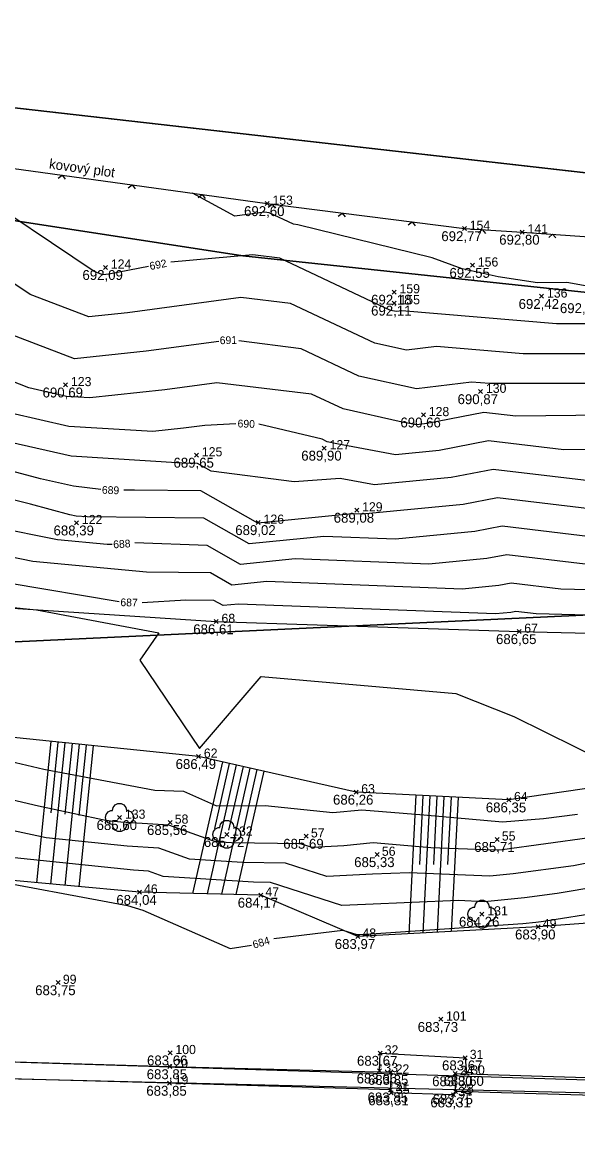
# Model space of a CAD drawing. Extents: x -439750 to -439180, y -1258684 to -1258308.
# Drawn here: x -439502.17 to -439486.43, y -1258511.26 to -1258479.7 of the extents above; entities that cross this region are included whole.
import ezdxf

# ---------------------------------------------------------------- set-up
doc = ezdxf.new("R2010")
doc.units = 0
for name, color, linetype in [('BODY', 7, 'Continuous'), ('CISBOD', 7, 'Continuous'), ('HRANA', 7, 'Continuous'), ('KATASTER', 7, 'Continuous'), ('POLOHOPIS', 7, 'Continuous'), ('SRAFY', 7, 'Continuous'), ('UOV', 7, 'Continuous'), ('VRSTEV', 7, 'Continuous'), ('VYSKY', 7, 'Continuous')]:
    doc.layers.add(name, color=color, linetype=linetype)

# ---------------------------------------------------------------- blocks, each defined once
blk = doc.blocks.new('313')
for points in [[(2, 0), (1.9, -0.43), (1.62, -0.78), (1.22, -0.97), (1, -1), (0.9, -1.43), (0.62, -1.78), (0.22, -1.97), (-0.23, -1.97), (-0.63, -1.78), (-0.91, -1.43), (-1.01, -1), (-1.23, -0.97), (-1.63, -0.78), (-1.91, -0.43), (-2.01, 0), (-1.91, 0.43), (-1.63, 0.78), (-1.23, 0.97), (-1.01, 1), (-0.91, 1.43), (-0.63, 1.78), (-0.23, 1.97), (0.22, 1.97), (0.62, 1.78), (0.9, 1.43), (1, 1), (1.22, 0.97), (1.62, 0.78), (1.9, 0.43), (2, 0)], [(-0.05, 0), (0, 0), (0.05, 0)]]:
    blk.add_lwpolyline(points)
blk = doc.blocks.new('KRIZEK')
for p, q in [((-2, 0), (2, 0)), ((0, 2), (0, -2))]:
    blk.add_line(p, q)
blk = doc.blocks.new('2123')
blk.add_lwpolyline([(-0.5, -0.5), (0, 0), (0.5, -0.5)])

msp = doc.modelspace()

# ---------------------------------------------------------------- linework, layer by layer
at = {"layer": 'HRANA'}
for points in [[(-439511.54, -1258493.8), (-439507.75, -1258495.43), (-439503.31, -1258496.25), (-439496.67, -1258496.69), (-439488.09, -1258496.97), (-439481.73, -1258497.12), (-439481.16, -1258497.23), (-439475.66, -1258497.77), (-439471.49, -1258498.09)], [(-439471.88, -1258500.9), (-439476.61, -1258500.46), (-439482.49, -1258500.91), (-439485.2, -1258501.28), (-439488.38, -1258501.74), (-439492.71, -1258501.52), (-439497.17, -1258500.51), (-439503.07, -1258499.91), (-439506.02, -1258500.06)], [(-439475.58, -1258504.53), (-439478.3, -1258506.13), (-439479.11, -1258504.72), (-439487.55, -1258505.34), (-439492.66, -1258505.61), (-439495.41, -1258504.44), (-439498.85, -1258504.36), (-439505, -1258503.79), (-439507.43, -1258504.94)]]:
    msp.add_lwpolyline(points, dxfattribs=at)
at = {"layer": 'KATASTER'}
for points in [[(-439462.74, -1258442.73), (-439465.13, -1258459.21), (-439469.01, -1258485.93), (-439514.85, -1258480.71), (-439509.68, -1258462.08), (-439512.86, -1258458.3), (-439516.51, -1258455.4), (-439520.66, -1258452.66), (-439525.5, -1258450.78), (-439531.73, -1258450.85), (-439536.69, -1258451.87), (-439541.07, -1258454.21), (-439546.64, -1258459.47)], [(-439546.64, -1258459.47), (-439541.07, -1258454.21), (-439536.69, -1258451.87), (-439531.73, -1258450.85), (-439525.5, -1258450.78), (-439520.66, -1258452.66), (-439516.51, -1258455.4), (-439512.86, -1258458.3), (-439509.68, -1258462.08), (-439514.85, -1258480.71), (-439515.19, -1258481.93), (-439503.22, -1258485.2), (-439495.92, -1258486.32), (-439485.72, -1258487.41), (-439470.33, -1258487.62), (-439429.22, -1258494.1), (-439415.96, -1258495.89), (-439399.97, -1258496.98), (-439400.54, -1258499.28), (-439484.47, -1258496.42), (-439507.21, -1258497.49), (-439520.19, -1258486.95), (-439538.17, -1258484.88), (-439548.5, -1258497.7)], [(-439548.5, -1258497.7), (-439538.17, -1258484.88), (-439520.19, -1258486.95), (-439507.21, -1258497.49), (-439484.47, -1258496.42), (-439400.54, -1258499.28), (-439387.09, -1258499.74), (-439411.19, -1258562.66), (-439413.56, -1258566.65), (-439437.77, -1258626.82), (-439438.12, -1258627.38), (-439482.75, -1258611.76), (-439518.67, -1258591.95), (-439550.54, -1258581.84), (-439567.51, -1258574.36), (-439597.45, -1258561.13)]]:
    msp.add_lwpolyline(points, dxfattribs=at)
for points in [[(-439515.19, -1258481.93), (-439514.85, -1258480.71), (-439469.01, -1258485.93), (-439399.61, -1258493.83), (-439399.2, -1258493.87), (-439399.97, -1258496.98), (-439415.96, -1258495.89), (-439429.22, -1258494.1), (-439470.33, -1258487.62), (-439485.72, -1258487.41), (-439495.92, -1258486.32), (-439503.22, -1258485.2)], [(-439543.31, -1258507.99), (-439510.11, -1258508.88), (-439509.96, -1258507.11), (-439505.22, -1258507.33), (-439505.26, -1258509.08), (-439479.78, -1258509.87), (-439475.62, -1258505.39), (-439475.25, -1258505.73), (-439479.41, -1258510.21), (-439505.77, -1258509.57), (-439505.73, -1258507.82), (-439509.5, -1258507.65), (-439509.65, -1258509.42), (-439543.32, -1258508.49)]]:
    msp.add_lwpolyline(points, close=True, dxfattribs=at)
at = {"layer": 'POLOHOPIS'}
for points in [[(-439511.93, -1258482.54), (-439503.64, -1258483.68), (-439495.23, -1258484.84), (-439489.64, -1258485.55), (-439488, -1258485.65), (-439480.93, -1258486.14), (-439472.63, -1258486.56)], [(-439491.72, -1258509.46), (-439491.73, -1258509.96), (-439498, -1258509.77), (-439506.04, -1258509.55), (-439505.93, -1258507.56)], [(-439505.93, -1258507.56), (-439505.43, -1258507.59), (-439505.49, -1258509.07), (-439497.99, -1258509.3), (-439491.72, -1258509.46)], [(-439492.04, -1258509.42), (-439492.03, -1258508.92), (-439489.62, -1258509.05), (-439489.58, -1258509.49)], [(-439489.89, -1258510.01), (-439489.95, -1258510.1), (-439491.71, -1258510.04), (-439491.73, -1258509.96)]]:
    msp.add_lwpolyline(points, dxfattribs=at)
msp.add_lwpolyline([(-439475.72, -1258505.59), (-439475.5, -1258505.84), (-439480.09, -1258510.29), (-439489.89, -1258510.01), (-439489.9, -1258509.5), (-439480.3, -1258509.79), (-439476.09, -1258505.71)], close=True, dxfattribs=at)
at = {"layer": 'SRAFY'}
for p, q in [((-439501.355, -1258500.084), (-439501.762, -1258504.09)), ((-439500.957, -1258500.125), (-439501.364, -1258504.127)), ((-439501.156, -1258500.105), (-439501.359, -1258502.107)), ((-439500.559, -1258500.165), (-439500.965, -1258504.164)), ((-439500.758, -1258500.145), (-439500.961, -1258502.145)), ((-439500.36, -1258500.186), (-439500.563, -1258502.184)), ((-439500.161, -1258500.206), (-439500.567, -1258504.201)), ((-439496.495, -1258500.663), (-439497.34, -1258504.395)), ((-439496.105, -1258500.751), (-439496.932, -1258504.405)), ((-439496.3, -1258500.707), (-439496.718, -1258502.553)), ((-439495.91, -1258500.795), (-439496.319, -1258502.602)), ((-439495.715, -1258500.84), (-439496.524, -1258504.414)), ((-439495.324, -1258500.928), (-439496.116, -1258504.424)), ((-439495.52, -1258500.884), (-439495.92, -1258502.651)), ((-439491.016, -1258501.606), (-439491.215, -1258505.534)), ((-439490.816, -1258501.616), (-439490.915, -1258503.57)), ((-439490.616, -1258501.626), (-439490.814, -1258505.512)), ((-439490.416, -1258501.637), (-439490.515, -1258503.569)), ((-439490.217, -1258501.647), (-439490.412, -1258505.491)), ((-439490.017, -1258501.657), (-439490.114, -1258503.569)), ((-439489.817, -1258501.667), (-439490.01, -1258505.47))]:
    msp.add_line(p, q, dxfattribs=at)
at = {"layer": 'UOV'}
msp.add_lwpolyline([(-439484.47, -1258496.42), (-439507.21, -1258497.49), (-439513.68, -1258492.23), (-439512.62, -1258492.23), (-439510.04, -1258487.61), (-439512.85, -1258480.94), (-439399.2, -1258493.87), (-439444.59, -1258496.79), (-439457.07, -1258497.35)], close=True, dxfattribs=at)
at = {"layer": 'VRSTEV'}
for points in [[(-439498.592, -1258486.625), (-439499.716, -1258486.844), (-439499.882, -1258486.862), (-439500.133, -1258486.766), (-439503.739, -1258484.346), (-439504.829, -1258483.901), (-439505.445, -1258483.432)], [(-439472.563, -1258487.239), (-439474.364, -1258487.755), (-439475.068, -1258487.75), (-439481.431, -1258487.77), (-439481.982, -1258487.475), (-439485.316, -1258487.329), (-439486.733, -1258487.079), (-439487.567, -1258487.084), (-439488.686, -1258486.915), (-439489.699, -1258486.689), (-439490.553, -1258486.376), (-439494.362, -1258485.445), (-439494.481, -1258485.427), (-439495.169, -1258485.102), (-439495.299, -1258485.087), (-439496.141, -1258485.2), (-439497.343, -1258484.549)], [(-439496.598, -1258488.747), (-439498.657, -1258489.027), (-439500.691, -1258489.246), (-439503.758, -1258488.068), (-439504.242, -1258487.743), (-439504.714, -1258487.551), (-439506.398, -1258486.559), (-439507.252, -1258486.214), (-439507.761, -1258485.907), (-439508.368, -1258485.633), (-439509.881, -1258484.987)], [(-439496.117, -1258491.08), (-439496.994, -1258491.129), (-439497.598, -1258491.21), (-439498.471, -1258491.304), (-439500.847, -1258491.155), (-439503.327, -1258490.595), (-439503.763, -1258490.479), (-439504.298, -1258490.324), (-439506.612, -1258489.211), (-439507.713, -1258488.761), (-439507.997, -1258488.59), (-439510.978, -1258487.248), (-439511.323, -1258487.078), (-439512.748, -1258486.152)], [(-439472.387, -1258489.02), (-439474.074, -1258489.503), (-439475.335, -1258489.453), (-439480.066, -1258489.43), (-439482.054, -1258489.252), (-439482.296, -1258489.125), (-439483.548, -1258489.103), (-439484.957, -1258489.077), (-439486.022, -1258489.098), (-439487.975, -1258489.098), (-439490.426, -1258488.894), (-439491.279, -1258488.999), (-439492.179, -1258488.799), (-439494.568, -1258487.671), (-439495.977, -1258487.503), (-439499.186, -1258487.936), (-439500.286, -1258488.054), (-439501.945, -1258487.417), (-439503.99, -1258486.045)], [(-439476.105, -1258488.582), (-439480.759, -1258488.607), (-439481.744, -1258488.519), (-439482.151, -1258488.307), (-439482.769, -1258488.296), (-439485.7, -1258488.243), (-439486.167, -1258488.252), (-439487.024, -1258488.252), (-439491.41, -1258487.886), (-439491.566, -1258487.905), (-439491.73, -1258487.868), (-439494.869, -1258486.386), (-439495.638, -1258486.295), (-439497.956, -1258486.501)], [(-439499.942, -1258492.947), (-439500.712, -1258492.853), (-439501.653, -1258492.64), (-439504.346, -1258491.923), (-439506.411, -1258491.327), (-439507.175, -1258491.189), (-439507.403, -1258491.125), (-439509.854, -1258490.5), (-439509.991, -1258490.431), (-439510.441, -1258490.117), (-439512.406, -1258488.742), (-439513.493, -1258488.215)], [(-439475.314, -1258490.305), (-439475.741, -1258490.27), (-439479.372, -1258490.252), (-439482.364, -1258489.984), (-439482.442, -1258489.944), (-439484.031, -1258489.915), (-439484.276, -1258489.92), (-439484.437, -1258489.916), (-439485.877, -1258489.944), (-439488.927, -1258489.945), (-439489.442, -1258489.902), (-439490.993, -1258490.093), (-439492.627, -1258489.73), (-439494.268, -1258488.955), (-439496.033, -1258488.729)], [(-439472.211, -1258490.8), (-439473.567, -1258491.189), (-439476.146, -1258491.087), (-439478.679, -1258491.074), (-439481.498, -1258490.822), (-439482.08, -1258490.844), (-439482.855, -1258490.839), (-439484.36, -1258490.873), (-439485.63, -1258490.838), (-439488.18, -1258490.87), (-439489.085, -1258490.762), (-439490.69, -1258491.079), (-439490.995, -1258491.108), (-439491.403, -1258491.032), (-439493.076, -1258490.661), (-439493.968, -1258490.239), (-439496.655, -1258489.92), (-439498.128, -1258490.119), (-439500.255, -1258490.347), (-439500.914, -1258490.306), (-439501.983, -1258490.065), (-439503.965, -1258489.291)], [(-439499.624, -1258494.501), (-439499.763, -1258494.503), (-439501.172, -1258494.367), (-439502.967, -1258494.008), (-439503.727, -1258493.818), (-439506.254, -1258493.695), (-439506.65, -1258493.624), (-439508.73, -1258493.037), (-439509.157, -1258492.928), (-439511.375, -1258491.815), (-439511.542, -1258491.699), (-439512.462, -1258491.178), (-439514.064, -1258489.772)], [(-439475.26, -1258491.994), (-439476.551, -1258491.903), (-439477.986, -1258491.896), (-439479.582, -1258491.753), (-439481.265, -1258491.818), (-439483.507, -1258491.804), (-439484.443, -1258491.825), (-439485.233, -1258491.803), (-439486.819, -1258491.823), (-439488.956, -1258491.568), (-439490.352, -1258491.844), (-439491.592, -1258491.961), (-439493.255, -1258491.651), (-439493.524, -1258491.591), (-439493.668, -1258491.523), (-439495.465, -1258491.097)], [(-439472.035, -1258492.581), (-439473.06, -1258492.875), (-439476.956, -1258492.72), (-439477.292, -1258492.718), (-439477.666, -1258492.685), (-439480.451, -1258492.791), (-439484.16, -1258492.769), (-439484.526, -1258492.777), (-439484.836, -1258492.768), (-439485.457, -1258492.776), (-439488.827, -1258492.374), (-439490.015, -1258492.609), (-439492.189, -1258492.814), (-439493.159, -1258492.633), (-439494.463, -1258492.732), (-439496.81, -1258492.428), (-439497.202, -1258492.206), (-439497.639, -1258492.201), (-439500.78, -1258492.004), (-439502.49, -1258491.617)], [(-439499.419, -1258496.131), (-439502.566, -1258495.595), (-439503.422, -1258495.423), (-439504.557, -1258495.373), (-439507.32, -1258494.886), (-439508.241, -1258494.654), (-439511.358, -1258493.774), (-439511.535, -1258493.684), (-439511.767, -1258493.545), (-439512.138, -1258493.734), (-439514.308, -1258493.966), (-439514.614, -1258493.906), (-439514.907, -1258493.8), (-439516.709, -1258492.88)], [(-439471.859, -1258494.362), (-439472.552, -1258494.561), (-439475.47, -1258494.445), (-439476.642, -1258494.449), (-439478.185, -1258494.599), (-439479.016, -1258494.655), (-439479.854, -1258494.53), (-439479.962, -1258494.505), (-439483.814, -1258494.392), (-439485.521, -1258494.35), (-439488.568, -1258493.986), (-439489.34, -1258494.139), (-439491.593, -1258494.351), (-439493.625, -1258494.273), (-439495.736, -1258494.485), (-439497.018, -1258493.759), (-439500.331, -1258493.721), (-439500.645, -1258493.702), (-439500.816, -1258493.663), (-439501.939, -1258493.364), (-439504.272, -1258492.782)], [(-439475.638, -1258493.622), (-439476.42, -1258493.574), (-439476.901, -1258493.576), (-439477.533, -1258493.638), (-439479.183, -1258493.748), (-439479.636, -1258493.765), (-439480.795, -1258493.758), (-439484.379, -1258493.653), (-439484.827, -1258493.642), (-439488.698, -1258493.18), (-439489.677, -1258493.374), (-439492.539, -1258493.643), (-439492.819, -1258493.632), (-439495.489, -1258493.901), (-439497.11, -1258492.982), (-439498.985, -1258492.961), (-439499.291, -1258492.968)], [(-439475.803, -1258495.284), (-439476.384, -1258495.323), (-439478.305, -1258495.509), (-439478.903, -1258495.462), (-439480.211, -1258495.267), (-439480.441, -1258495.213), (-439483.25, -1258495.131), (-439486.215, -1258495.058), (-439488.439, -1258494.792), (-439489.002, -1258494.903), (-439490.646, -1258495.058), (-439494.432, -1258494.913), (-439495.983, -1258495.069), (-439496.926, -1258494.535), (-439498.974, -1258494.459)], [(-439471.682, -1258496.143), (-439472.045, -1258496.247), (-439473.568, -1258496.187), (-439476.126, -1258496.196), (-439477.361, -1258496.316), (-439479.751, -1258496.126), (-439480.567, -1258496.005), (-439480.92, -1258495.921), (-439482.685, -1258495.87), (-439486.909, -1258495.765), (-439488.31, -1258495.598), (-439488.665, -1258495.668), (-439489.7, -1258495.766), (-439495.238, -1258495.553), (-439496.231, -1258495.653), (-439496.834, -1258495.311), (-439498.649, -1258495.291), (-439501.869, -1258494.981), (-439503.527, -1258494.649)], [(-439476.205, -1258497.104), (-439476.417, -1258497.123), (-439480.599, -1258496.79), (-439480.924, -1258496.742), (-439481.399, -1258496.63), (-439482.121, -1258496.609), (-439487.603, -1258496.473), (-439488.181, -1258496.404), (-439488.327, -1258496.433), (-439488.754, -1258496.473), (-439496.044, -1258496.193), (-439496.478, -1258496.237), (-439496.741, -1258496.088), (-439497.535, -1258496.079), (-439498.767, -1258496.153)], [(-439503.263, -1258496.208), (-439501.764, -1258496.352), (-439498.297, -1258497.004), (-439498.836, -1258497.78), (-439497.141, -1258500.285), (-439495.396, -1258498.244), (-439489.878, -1258498.731), (-439488.236, -1258499.379), (-439485.601, -1258500.682), (-439484.832, -1258500.732), (-439482.541, -1258499.428), (-439481.974, -1258499.483), (-439478.072, -1258499.422), (-439476.185, -1258499.258), (-439474.352, -1258498.853), (-439473.51, -1258497.935), (-439471.667, -1258497.928), (-439471.537, -1258497.933), (-439471.506, -1258497.924)], [(-439504.736, -1258499.078), (-439503.946, -1258499.955), (-439503.494, -1258500.418), (-439501.558, -1258500.873), (-439498.408, -1258501.466), (-439497.598, -1258501.499), (-439496.662, -1258501.914), (-439495.288, -1258501.904), (-439493.363, -1258502.099), (-439492.541, -1258502.019), (-439490.79, -1258502.163), (-439488.563, -1258502.359), (-439487.393, -1258502.267), (-439486.431, -1258502.145)], [(-439486.215, -1258503.548), (-439486.548, -1258503.609), (-439488.253, -1258503.838), (-439488.921, -1258503.899), (-439491.202, -1258503.806), (-439492.242, -1258503.849), (-439493.533, -1258503.913), (-439494.708, -1258503.531), (-439495.925, -1258503.518), (-439497.432, -1258503.422), (-439498.301, -1258503.111), (-439499.194, -1258503.057), (-439501.492, -1258502.817), (-439504.585, -1258502.154), (-439505.364, -1258501.867), (-439506.52, -1258500.68), (-439507.651, -1258500.254), (-439507.661, -1258500.251), (-439508.349, -1258499.736)], [(-439515.452, -1258501.003), (-439514.762, -1258501.87), (-439509.16, -1258502.167), (-439508.201, -1258502.461), (-439508.013, -1258502.532), (-439507.821, -1258502.729), (-439504.995, -1258503.769), (-439504.955, -1258503.778), (-439503.546, -1258503.925), (-439499.185, -1258504.733), (-439498.753, -1258504.867), (-439496.279, -1258505.951), (-439495.668, -1258505.858)], [(-439472.971, -1258501.97), (-439476.279, -1258501.767), (-439477.346, -1258502.118), (-439479.358, -1258502.256), (-439481.2, -1258502.365), (-439483.476, -1258502.369), (-439484.124, -1258502.487), (-439486.091, -1258502.82), (-439488.573, -1258503.153), (-439488.773, -1258503.171), (-439490.59, -1258503.098), (-439492.221, -1258502.963), (-439493.057, -1258503.045), (-439493.956, -1258503.089), (-439494.284, -1258502.983), (-439496.235, -1258502.961), (-439496.691, -1258502.932), (-439498.015, -1258502.46), (-439499.374, -1258502.377), (-439499.76, -1258502.337), (-439501.704, -1258501.92), (-439504.249, -1258501.323)], [(-439474.313, -1258503.287), (-439475.919, -1258503.188), (-439476.948, -1258503.527), (-439477.942, -1258504.172), (-439478.477, -1258503.918), (-439479.754, -1258503.994), (-439480.926, -1258503.996), (-439485.832, -1258504.199), (-439487.005, -1258504.398), (-439487.932, -1258504.522), (-439489.068, -1258504.626), (-439489.814, -1258504.596), (-439492.445, -1258504.703), (-439493.109, -1258504.736), (-439495.131, -1258504.079), (-439495.614, -1258504.074), (-439498.172, -1258503.912), (-439498.588, -1258503.763), (-439499.015, -1258503.737), (-439503.223, -1258503.297)], [(-439495.042, -1258505.673), (-439493.082, -1258505.43), (-439492.686, -1258505.559), (-439492.647, -1258505.557), (-439492.281, -1258505.542), (-439487.986, -1258505.241), (-439487.612, -1258505.207), (-439487.461, -1258505.187), (-439487.271, -1258505.155), (-439485.85, -1258504.932)]]:
    msp.add_lwpolyline(points, dxfattribs=at)

# ---------------------------------------------------------------- block references
at = {"layer": 'BODY', "xscale": 0.04, "yscale": 0.04000000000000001, "rotation": 44.977187}
for p in [(-439495.23, -1258484.84), (-439489.64, -1258485.55), (-439488, -1258485.65), (-439499.81, -1258486.65), (-439489.41, -1258486.59), (-439491.63, -1258487.35), (-439491.63, -1258487.66), (-439487.45, -1258487.47), (-439500.94, -1258489.98), (-439489.18, -1258490.17), (-439490.8, -1258490.83), (-439493.61, -1258491.77), (-439497.23, -1258491.97), (-439492.69, -1258493.53), (-439500.63, -1258493.89), (-439495.48, -1258493.88), (-439496.67, -1258496.69), (-439488.09, -1258496.97), (-439497.17, -1258500.51), (-439492.71, -1258501.52), (-439488.38, -1258501.74), (-439499.41, -1258502.24), (-439497.98, -1258502.38), (-439496.37, -1258502.72), (-439494.12, -1258502.77), (-439488.71, -1258502.86), (-439492.11, -1258503.29), (-439498.85, -1258504.36), (-439495.41, -1258504.44), (-439489.14, -1258504.98), (-439487.55, -1258505.34), (-439492.66, -1258505.61), (-439501.15, -1258506.92), (-439490.31, -1258507.96), (-439497.98, -1258508.91), (-439492.03, -1258508.92), (-439489.62, -1258509.05), (-439497.99, -1258509.3), (-439492.04, -1258509.42), (-439498, -1258509.77), (-439491.72, -1258509.46), (-439489.9, -1258509.5), (-439489.58, -1258509.49), (-439491.73, -1258509.96), (-439491.71, -1258510.04), (-439489.89, -1258510.01), (-439489.95, -1258510.1)]:
    msp.add_blockref('KRIZEK', p, dxfattribs=at)
at = {"layer": 'POLOHOPIS'}
for p, xscale, yscale, rotation in [((-439501.033, -1258484.04), 0.20000000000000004, 0.2, -7.860138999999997), ((-439499.051, -1258484.313), 0.20000000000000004, 0.2, -7.860138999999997), ((-439497.07, -1258484.586), 0.20000000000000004, 0.2, -7.860138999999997), ((-439495.089, -1258484.858), 0.19999999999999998, 0.2, -7.229885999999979), ((-439493.105, -1258485.11), 0.19999999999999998, 0.2, -7.229885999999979), ((-439491.121, -1258485.362), 0.19999999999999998, 0.2, -7.229885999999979), ((-439489.133, -1258485.581), 0.2, 0.19999999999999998, -3.5056600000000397), ((-439487.138, -1258485.71), 0.19999999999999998, 0.2, -3.964026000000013)]:
    msp.add_blockref('2123', p, dxfattribs=dict(at, xscale=xscale, yscale=yscale, rotation=rotation))
at = {"layer": 'POLOHOPIS', "xscale": 0.2, "yscale": 0.20000000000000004}
for p in [(-439499.41, -1258502.24), (-439496.37, -1258502.72), (-439489.14, -1258504.98)]:
    msp.add_blockref('313', p, dxfattribs=at)

# ---------------------------------------------------------------- texts
at = {"layer": 'CISBOD'}
for s, p in [('153', (-439495.078, -1258484.876)), ('154', (-439489.488, -1258485.586)), ('141', (-439487.848, -1258485.686)), ('124', (-439499.658, -1258486.686)), ('156', (-439489.258, -1258486.626)), ('159', (-439491.478, -1258487.386)), ('136', (-439487.298, -1258487.506)), ('155', (-439491.478, -1258487.696)), ('123', (-439500.788, -1258490.016)), ('130', (-439489.028, -1258490.206)), ('128', (-439490.648, -1258490.866)), ('127', (-439493.458, -1258491.806)), ('125', (-439497.078, -1258492.006)), ('129', (-439492.538, -1258493.566)), ('122', (-439500.478, -1258493.926)), ('126', (-439495.328, -1258493.916)), ('68', (-439496.522, -1258496.726)), ('67', (-439487.942, -1258497.006)), ('62', (-439497.022, -1258500.546)), ('63', (-439492.562, -1258501.556)), ('64', (-439488.232, -1258501.776)), ('133', (-439499.258, -1258502.276)), ('58', (-439497.847, -1258502.416)), ('132', (-439496.218, -1258502.756)), ('57', (-439493.987, -1258502.806)), ('55', (-439488.577, -1258502.896)), ('56', (-439491.977, -1258503.326)), ('46', (-439498.717, -1258504.396)), ('47', (-439495.277, -1258504.476)), ('131', (-439488.988, -1258505.016)), ('49', (-439487.417, -1258505.376)), ('48', (-439492.527, -1258505.646)), ('99', (-439501.017, -1258506.956)), ('101', (-439490.158, -1258507.996)), ('100', (-439497.828, -1258508.946)), ('32', (-439491.897, -1258508.956)), ('31', (-439489.487, -1258509.086)), ('20', (-439497.857, -1258509.336)), ('33', (-439491.907, -1258509.456)), ('22', (-439491.587, -1258509.496)), ('24', (-439489.767, -1258509.536)), ('30', (-439489.447, -1258509.526)), ('19', (-439497.848, -1258509.806)), ('21', (-439491.597, -1258509.996)), ('35', (-439491.577, -1258510.076)), ('34', (-439489.817, -1258510.136)), ('23', (-439489.757, -1258510.046))]:
    msp.add_text(s, height=0.26, dxfattribs=at).set_placement(p)
at = {"layer": 'POLOHOPIS'}
msp.add_text('kovový plot', height=0.28, rotation=352.14, dxfattribs=at).set_placement((-439501.42, -1258483.847))
at = {"layer": 'VRSTEV'}
for s, rotation, p in [('692', 11.23, (-439498.54, -1258486.727)), ('691', 1.604, (-439496.569, -1258488.829)), ('690', 358.167, (-439496.069, -1258491.184)), ('689', 358.167, (-439499.914, -1258493.064)), ('688', 3.724, (-439499.584, -1258494.613)), ('687', 358.625, (-439499.389, -1258496.25)), ('684', 16.741, (-439495.602, -1258505.961))]:
    msp.add_text(s, height=0.22, rotation=rotation, dxfattribs=at).set_placement(p)
at = {"layer": 'VYSKY'}
for s, p in [('692,60', (-439495.882, -1258485.196)), ('692,77', (-439490.292, -1258485.906)), ('692,80', (-439488.652, -1258486.006)), ('692,09', (-439500.462, -1258487.006)), ('692,55', (-439490.062, -1258486.946)), ('692,18', (-439492.282, -1258487.706)), ('692,42', (-439488.102, -1258487.826)), ('692,11', (-439492.282, -1258488.016)), ('692,39', (-439486.932, -1258487.946)), ('690,69', (-439501.592, -1258490.336)), ('690,87', (-439489.832, -1258490.526)), ('690,66', (-439491.452, -1258491.186)), ('689,90', (-439494.262, -1258492.126)), ('689,65', (-439497.882, -1258492.326)), ('689,08', (-439493.342, -1258493.886)), ('688,39', (-439501.282, -1258494.246)), ('689,02', (-439496.132, -1258494.236)), ('686,61', (-439497.322, -1258497.046)), ('686,65', (-439488.742, -1258497.326)), ('686,49', (-439497.822, -1258500.866)), ('686,26', (-439493.362, -1258501.876)), ('686,35', (-439489.032, -1258502.096)), ('685,60', (-439500.062, -1258502.596)), ('685,56', (-439498.632, -1258502.736)), ('685,72', (-439497.022, -1258503.076)), ('685,69', (-439494.772, -1258503.126)), ('685,71', (-439489.362, -1258503.216)), ('685,33', (-439492.762, -1258503.646)), ('684,04', (-439499.502, -1258504.716)), ('684,17', (-439496.062, -1258504.796)), ('684,26', (-439489.792, -1258505.336)), ('683,90', (-439488.202, -1258505.696)), ('683,97', (-439493.312, -1258505.966)), ('683,75', (-439501.802, -1258507.276)), ('683,73', (-439490.962, -1258508.316)), ('683,66', (-439498.632, -1258509.266)), ('683,67', (-439492.682, -1258509.276)), ('683,67', (-439490.272, -1258509.406)), ('683,85', (-439498.642, -1258509.656)), ('683,66', (-439492.692, -1258509.776)), ('683,85', (-439492.372, -1258509.816)), ('683,80', (-439490.552, -1258509.856)), ('683,60', (-439490.232, -1258509.846)), ('683,85', (-439498.652, -1258510.126)), ('683,85', (-439492.382, -1258510.316)), ('683,31', (-439492.362, -1258510.396)), ('683,31', (-439490.602, -1258510.456)), ('683,75', (-439490.542, -1258510.366))]:
    msp.add_text(s, height=0.28, dxfattribs=at).set_placement(p)

doc.saveas('drawing.dxf')
